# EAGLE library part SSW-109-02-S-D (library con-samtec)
THROUGH-HOLE .025" SQ POST SOCKET Source: Samtec SSW.pdf
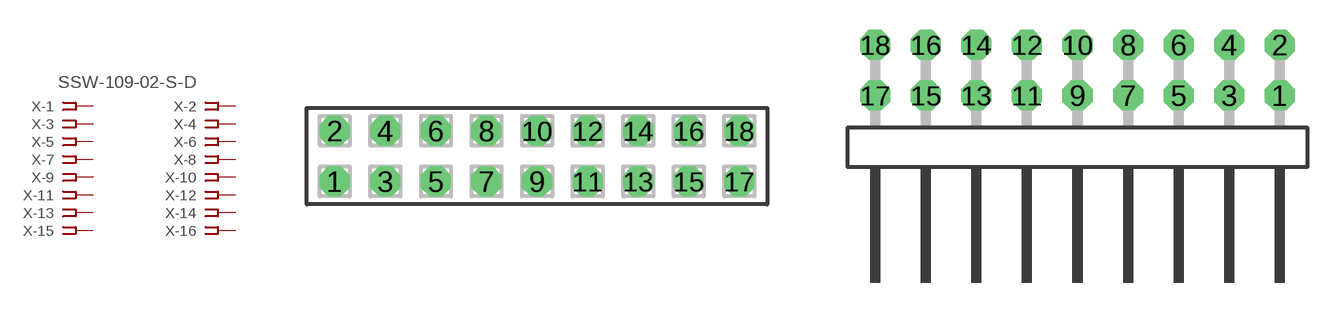
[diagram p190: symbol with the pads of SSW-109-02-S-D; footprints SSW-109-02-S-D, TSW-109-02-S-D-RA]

Designator prefix X; gates -1=FPINV -2=FPIN -3=FPIN -4=FPIN -5=FPIN -6=FPIN -7=FPIN -8=FPIN -9=FPIN -10=FPIN -11=FPIN -12=FPIN -13=FPIN -14=FPIN -15=FPIN -16=FPIN -17=FPIN -18=FPIN

## SSW-109-02-S-D (MPN: SSW-109-02-S-D; OC_FARNELL: unknown; OC_NEWARK: 11P9463)  [SSW-109-02-S-D]
1  -1:1  pas
2  -2:1  pas
3  -3:1  pas
4  -4:1  pas
5  -5:1  pas
6  -6:1  pas
7  -7:1  pas
8  -8:1  pas
9  -9:1  pas
10  -10:1  pas
11  -11:1  pas
12  -12:1  pas
13  -13:1  pas
14  -14:1  pas
15  -15:1  pas
16  -16:1  pas
17  -17:1  pas
18  -18:1  pas

## SSW-109-02-S-D-RA (MPN: SSW-109-02-S-D-RA; OC_FARNELL: unknown; OC_NEWARK: 11P9464)  [TSW-109-02-S-D-RA]
Pads as for SSW-109-02-S-D

## Footprint SSW-109-02-S-D (pad centres in mm)
THROUGH-HOLE .025" SQ POST SOCKET Source: Samtec SSW.pdf
drill 1 pad 1.5 octagon: 1 -10.16,-1.27; 2 -10.16,1.27; 3 -7.62,-1.27; 4 -7.62,1.27; 5 -5.08,-1.27; 6 -5.08,1.27; 7 -2.54,-1.27; 8 -2.54,1.27; 9 0,-1.27; 10 0,1.27; 11 2.54,-1.27; 12 2.54,1.27; 13 5.08,-1.27; 14 5.08,1.27; 15 7.62,-1.27; 16 7.62,1.27; 17 10.16,-1.27; 18 10.16,1.27

## Footprint TSW-109-02-S-D-RA (pad centres in mm)
THROUGH-HOLE .025" SQ POST HEADER Source: Samtec TSW.pdf
drill 1 pad 1.5 octagon: 1 10.16,1.524; 2 10.16,4.064; 3 7.62,1.524; 4 7.62,4.064; 5 5.08,1.524; 6 5.08,4.064; 7 2.54,1.524; 8 2.54,4.064; 9 0,1.524; 10 0,4.064; 11 -2.54,1.524; 12 -2.54,4.064; 13 -5.08,1.524; 14 -5.08,4.064; 15 -7.62,1.524; 16 -7.62,4.064; 17 -10.16,1.524; 18 -10.16,4.064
